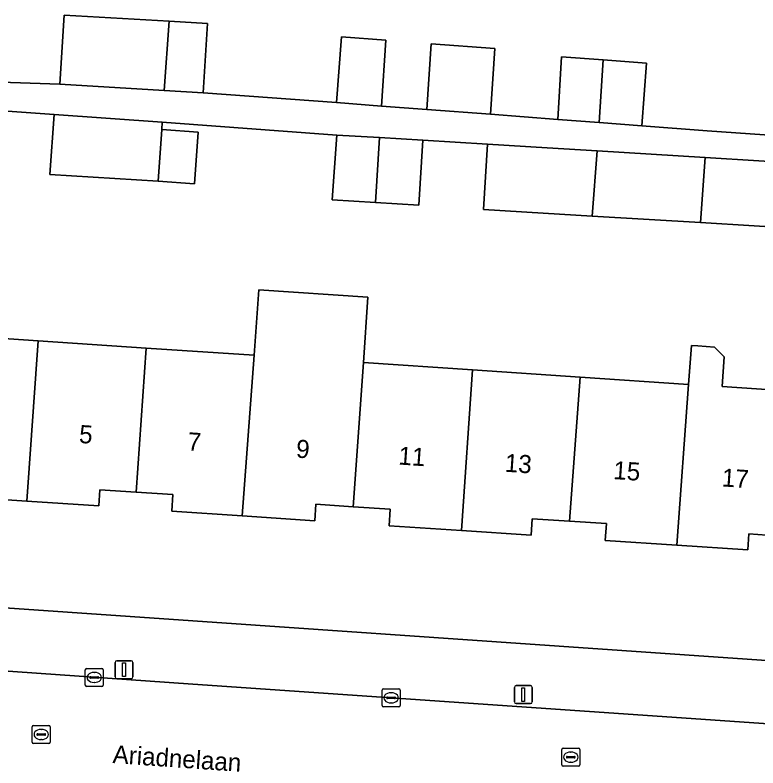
# Model space of a CAD drawing. Extents: x 161848 to 162726, y 385382 to 386521.
# Drawn here: x 162033.12 to 162074.32, y 385520.46 to 385562.19 of the extents above; entities that cross this region are included whole.
import ezdxf

# ---------------------------------------------------------------- set-up
doc = ezdxf.new("R2010")
doc.units = 0
for name, color, linetype in [('IMGEO_Erf', 7, 'Continuous'), ('IMGEO_Kolk', 7, 'Continuous'), ('IMGEO_Lichtmast', 7, 'Continuous'), ('IMGEO_Openbare_ruimte_label', 7, 'Continuous'), ('IMGEO_Pand', 7, 'Continuous'), ('IMGEO_Pand_nummerreeks', 7, 'Continuous'), ('IMGEO_Rijbaan_lokaal_open', 7, 'Continuous'), ('IMGEO_Rioolput', 7, 'Continuous'), ('IMGEO_Voetpad_open', 7, 'Continuous')]:
    doc.layers.add(name, color=color, linetype=linetype)

msp = doc.modelspace()

# ---------------------------------------------------------------- linework, layer by layer
at = {"layer": 'IMGEO_Erf'}
for points in [[(162031.758, 385558.476), (162035.606, 385558.348), (162035.835, 385562.186), (162041.661, 385561.839), (162043.785, 385561.712), (162043.556, 385557.874), (162050.942, 385557.333), (162051.218, 385560.974), (162053.681, 385560.788), (162053.437, 385557.144), (162055.957, 385556.953), (162056.201, 385560.597), (162059.728, 385560.33), (162059.48, 385556.687), (162063.214, 385556.405), (162063.426, 385559.879), (162065.736, 385559.703), (162068.137, 385559.521), (162067.889, 385556.051), (162071.496, 385555.778), (162083.419, 385554.931)], [(162059.32, 385555.025), (162055.736, 385555.244), (162055.516, 385551.647), (162053.109, 385551.794), (162050.703, 385551.941), (162050.958, 385555.536), (162041.286, 385556.253), (162041.258, 385555.842), (162043.269, 385555.704), (162043.072, 385552.833), (162041.061, 385552.971), (162035.054, 385553.353), (162035.289, 385556.672), (162031.648, 385556.926), (162031.387, 385553.375), (162031.148, 385550.134), (162028.864, 385550.302), (162026.141, 385550.502), (162026.329, 385553.046), (162022.838, 385553.268), (162014.712, 385553.868), (162013.874, 385541.566), (162013.328, 385533.953)], [(162091.723, 385527.993), (162092.1, 385533.688), (162092.534, 385540.24), (162093.077, 385548.435), (162093.358, 385552.663), (162090.214, 385552.863), (162089.88, 385548.648), (162089.229, 385548.691), (162082.901, 385549.112), (162082.968, 385549.956), (162077.085, 385550.316), (162071.126, 385550.681), (162065.134, 385551.048), (162062.406, 385551.215), (162059.099, 385551.418), (162059.32, 385555.025)], [(162028.431, 385544.533), (162034.4, 385544.133), (162040.398, 385543.731), (162046.373, 385543.331), (162046.638, 385546.964), (162052.692, 385546.546), (162052.437, 385542.925), (162058.492, 385542.519), (162064.463, 385542.12), (162070.474, 385541.717), (162070.631, 385543.878), (162070.981, 385543.852), (162071.911, 385543.785), (162072.453, 385543.249), (162072.333, 385541.592), (162076.413, 385541.319)], [(162075.813, 385533.294), (162073.82, 385533.427), (162073.761, 385532.541), (162069.827, 385532.804), (162065.854, 385533.07), (162065.916, 385533.998), (162063.864, 385534.135), (162061.803, 385534.273), (162061.741, 385533.353), (162057.871, 385533.612), (162053.861, 385533.881), (162053.922, 385534.795), (162051.875, 385534.932), (162049.799, 385535.071), (162049.738, 385534.162), (162045.724, 385534.431), (162041.813, 385534.693), (162041.874, 385535.609), (162039.839, 385535.745), (162037.823, 385535.88), (162037.763, 385534.98), (162033.771, 385535.247), (162029.858, 385535.509)], [(162016.402, 385530.453), (162018.636, 385530.301), (162087.624, 385525.529), (162089.014, 385525.433)]]:
    msp.add_lwpolyline(points, dxfattribs=at)
at = {"layer": 'IMGEO_Kolk'}
for p, q in [((162037.014, 385525.047), (162037.014, 385525.899)), ((162037.089, 385525.973), (162037.941, 385525.973)), ((162038.015, 385525.899), (162038.015, 385525.047)), ((162037.273, 385525.467), (162037.273, 385525.479)), ((162037.316, 385525.516), (162037.714, 385525.516)), ((162037.502, 385525.753), (162037.527, 385525.753)), ((162037.757, 385525.479), (162037.757, 385525.467)), ((162037.711, 385525.43), (162037.313, 385525.43)), ((162037.525, 385525.193), (162037.5, 385525.193)), ((162037.941, 385524.973), (162037.089, 385524.973)), ((162053.474, 385523.918), (162053.474, 385524.77)), ((162053.549, 385524.844), (162054.401, 385524.844)), ((162054.475, 385524.77), (162054.475, 385523.918)), ((162053.733, 385524.338), (162053.733, 385524.35)), ((162054.171, 385524.301), (162053.773, 385524.301)), ((162053.776, 385524.387), (162054.174, 385524.387)), ((162053.962, 385524.624), (162053.987, 385524.624)), ((162054.217, 385524.35), (162054.217, 385524.338)), ((162054.401, 385523.844), (162053.549, 385523.844)), ((162053.985, 385524.064), (162053.96, 385524.064))]:
    msp.add_line(p, q, dxfattribs=at)
for points in [[(162037.014, 385525.047), (162037.014, 385525.899)], [(162037.089, 385525.973), (162037.941, 385525.973)], [(162038.015, 385525.899), (162038.015, 385525.047)], [(162037.941, 385524.973), (162037.089, 385524.973)], [(162053.474, 385523.918), (162053.474, 385524.77)], [(162053.549, 385524.844), (162054.401, 385524.844)], [(162054.475, 385524.77), (162054.475, 385523.918)], [(162054.401, 385523.844), (162053.549, 385523.844)]]:
    msp.add_lwpolyline(points, dxfattribs=at)
for centre, radius, start, end in [((162037.091, 385525.897), 0.0765, 91.552, 178.448), ((162037.091, 385525.897), 0.0765, 91.552, 178.448), ((162037.939, 385525.897), 0.0765, 1.552, 88.448), ((162037.939, 385525.897), 0.0765, 1.552, 88.448), ((162037.313, 385525.476), 0.0403, 85.8775, 175.7526), ((162037.31, 385525.466), 0.0366, 178.938, 274.7102), ((162037.714, 385525.473), 0.043, 264.8664, 352.4533), ((162037.718, 385525.478), 0.0386, 1.7309, 96.639), ((162037.091, 385525.049), 0.0765, 181.552, 268.448), ((162037.091, 385525.049), 0.0765, 181.552, 268.448), ((162037.939, 385525.049), 0.0765, 271.552, 358.448), ((162037.939, 385525.049), 0.0765, 271.552, 358.448), ((162053.551, 385524.768), 0.0765, 91.552, 178.448), ((162053.551, 385524.768), 0.0765, 91.552, 178.448), ((162054.399, 385524.768), 0.0765, 1.552, 88.448), ((162054.399, 385524.768), 0.0765, 1.552, 88.448), ((162053.773, 385524.347), 0.0403, 85.8775, 175.7526), ((162053.77, 385524.337), 0.0366, 178.938, 274.7102), ((162054.174, 385524.344), 0.043, 264.8664, 352.4533), ((162054.178, 385524.349), 0.0386, 1.7309, 96.639), ((162053.551, 385523.92), 0.0765, 181.552, 268.448), ((162053.551, 385523.92), 0.0765, 181.552, 268.448), ((162054.399, 385523.92), 0.0765, 271.552, 358.448), ((162054.399, 385523.92), 0.0765, 271.552, 358.448)]:
    msp.add_arc(centre, radius, start, end, dxfattribs=at)
for centre, major_axis, ratio, start_param, end_param in [((162037.501, 385525.473), (-0.387, 0.002), 0.722429, 4.712389, 7.853982), ((162037.526, 385525.473), (-0.39, 0.002), 0.717154, 1.570796, 4.712389), ((162053.961, 385524.344), (-0.387, 0.002), 0.722429, 4.712389, 7.853982), ((162053.986, 385524.344), (-0.39, 0.002), 0.717154, 1.570796, 4.712389)]:
    msp.add_ellipse(centre, major_axis=major_axis, ratio=ratio, start_param=start_param, end_param=end_param, dxfattribs=at)
at = {"layer": 'IMGEO_Lichtmast'}
for p, q in [((162038.668, 385525.501), (162038.668, 385526.301)), ((162038.668, 385526.301), (162038.668, 385525.501)), ((162038.768, 385526.401), (162039.558, 385526.401)), ((162039.558, 385526.401), (162038.768, 385526.401)), ((162039.658, 385526.301), (162039.658, 385525.501)), ((162039.658, 385525.501), (162039.658, 385526.301)), ((162039.558, 385525.401), (162038.768, 385525.401)), ((162038.768, 385525.401), (162039.558, 385525.401)), ((162060.81, 385524.124), (162060.81, 385524.924)), ((162060.81, 385524.924), (162060.81, 385524.124)), ((162060.91, 385525.024), (162061.7, 385525.024)), ((162061.7, 385525.024), (162060.91, 385525.024)), ((162061.8, 385524.924), (162061.8, 385524.124)), ((162061.8, 385524.124), (162061.8, 385524.924)), ((162061.7, 385524.024), (162060.91, 385524.024)), ((162060.91, 385524.024), (162061.7, 385524.024))]:
    msp.add_line(p, q, dxfattribs=at)
for points in [[(162039.088, 385526.276), (162039.238, 385526.276), (162039.238, 385525.526), (162039.088, 385525.526), (162039.088, 385526.276)], [(162061.23, 385524.899), (162061.38, 385524.899), (162061.38, 385524.149), (162061.23, 385524.149), (162061.23, 385524.899)]]:
    msp.add_lwpolyline(points, dxfattribs=at)
for centre, start, end in [((162038.768, 385526.301), 90, 180), ((162038.768, 385526.301), 90, 180), ((162039.558, 385526.301), 0, 90), ((162039.558, 385526.301), 360, 90), ((162038.768, 385525.501), 180, 270), ((162038.768, 385525.501), 180, 270), ((162039.558, 385525.501), 270, 0), ((162039.558, 385525.501), 270, 0), ((162060.91, 385524.924), 90, 180), ((162060.91, 385524.924), 90, 180), ((162061.7, 385524.924), 0, 90), ((162061.7, 385524.924), 360, 90), ((162060.91, 385524.124), 180, 270), ((162060.91, 385524.124), 180, 270), ((162061.7, 385524.124), 270, 0), ((162061.7, 385524.124), 270, 0)]:
    msp.add_arc(centre, 0.1, start, end, dxfattribs=at)
at = {"layer": 'IMGEO_Pand'}
for points in [[(162035.835, 385562.186), (162035.606, 385558.348), (162041.398, 385558.003), (162041.661, 385561.839)], [(162043.556, 385557.874), (162043.785, 385561.712), (162041.661, 385561.839), (162041.398, 385558.003)], [(162053.681, 385560.788), (162051.218, 385560.974), (162050.942, 385557.333), (162053.437, 385557.144)], [(162055.957, 385556.953), (162059.48, 385556.687), (162059.728, 385560.33), (162056.201, 385560.597)], [(162065.736, 385559.703), (162063.426, 385559.879), (162063.214, 385556.405), (162065.523, 385556.23)], [(162065.736, 385559.703), (162065.523, 385556.23), (162067.889, 385556.051), (162068.137, 385559.521)], [(162041.258, 385555.842), (162041.286, 385556.253), (162035.289, 385556.672), (162035.054, 385553.353), (162041.061, 385552.971)], [(162041.061, 385552.971), (162043.072, 385552.833), (162043.269, 385555.704), (162041.258, 385555.842)], [(162053.109, 385551.794), (162053.329, 385555.391), (162050.958, 385555.536), (162050.703, 385551.941)], [(162053.329, 385555.391), (162053.109, 385551.794), (162055.516, 385551.647), (162055.736, 385555.244)], [(162065.405, 385554.653), (162062.627, 385554.823), (162059.32, 385555.025), (162059.099, 385551.418), (162062.406, 385551.215), (162065.134, 385551.048)], [(162065.134, 385551.048), (162071.126, 385550.681), (162071.388, 385554.286), (162065.405, 385554.653)], [(162071.126, 385550.681), (162077.085, 385550.316), (162077.354, 385553.921), (162071.388, 385554.286)], [(162052.437, 385542.925), (162052.692, 385546.546), (162046.638, 385546.964), (162046.373, 385543.331), (162045.724, 385534.431), (162049.738, 385534.162), (162049.799, 385535.071), (162051.875, 385534.932)], [(162034.4, 385544.133), (162028.431, 385544.533), (162027.865, 385536.544), (162029.919, 385536.407), (162029.858, 385535.509), (162033.771, 385535.247)], [(162040.398, 385543.731), (162034.4, 385544.133), (162033.771, 385535.247), (162037.763, 385534.98), (162037.823, 385535.88), (162039.839, 385535.745)], [(162076.413, 385541.319), (162072.333, 385541.592), (162072.453, 385543.249), (162071.911, 385543.785), (162070.981, 385543.852), (162070.631, 385543.878), (162070.474, 385541.717), (162069.827, 385532.804), (162073.761, 385532.541), (162073.82, 385533.427), (162075.813, 385533.294)], [(162039.839, 385535.745), (162041.874, 385535.609), (162041.813, 385534.693), (162045.724, 385534.431), (162046.373, 385543.331), (162040.398, 385543.731)], [(162058.492, 385542.519), (162052.437, 385542.925), (162051.875, 385534.932), (162053.922, 385534.795), (162053.861, 385533.881), (162057.871, 385533.612)], [(162064.463, 385542.12), (162058.492, 385542.519), (162057.871, 385533.612), (162061.741, 385533.353), (162061.803, 385534.273), (162063.864, 385534.135)], [(162063.864, 385534.135), (162065.916, 385533.998), (162065.854, 385533.07), (162069.827, 385532.804), (162070.474, 385541.717), (162064.463, 385542.12)]]:
    msp.add_lwpolyline(points, close=True, dxfattribs=at)
at = {"layer": 'IMGEO_Rijbaan_lokaal_open'}
for points in [[(162042.972, 385525.1), (162018.004, 385526.862), (162015.014, 385527.081), (162014.628, 385519.918), (162018.299, 385519.675), (162054.531, 385517.227), (162072.879, 385515.977)], [(162086.98, 385522.071), (162042.972, 385525.1)]]:
    msp.add_lwpolyline(points, dxfattribs=at)
at = {"layer": 'IMGEO_Rioolput'}
for p, q in [((162034.073, 385521.886), (162034.073, 385522.738)), ((162034.148, 385522.812), (162035, 385522.812)), ((162034.561, 385522.592), (162034.586, 385522.592)), ((162035.074, 385522.738), (162035.074, 385521.886)), ((162034.332, 385522.306), (162034.332, 385522.318)), ((162034.77, 385522.269), (162034.372, 385522.269)), ((162034.375, 385522.355), (162034.773, 385522.355)), ((162034.816, 385522.318), (162034.816, 385522.306)), ((162035, 385521.812), (162034.148, 385521.812)), ((162034.584, 385522.032), (162034.559, 385522.032)), ((162063.438, 385520.63), (162063.438, 385521.482)), ((162063.513, 385521.556), (162064.365, 385521.556)), ((162063.926, 385521.336), (162063.951, 385521.336)), ((162064.439, 385521.482), (162064.439, 385520.63)), ((162063.697, 385521.05), (162063.697, 385521.062)), ((162064.135, 385521.013), (162063.737, 385521.013)), ((162063.74, 385521.099), (162064.138, 385521.099)), ((162064.181, 385521.062), (162064.181, 385521.05)), ((162064.365, 385520.556), (162063.513, 385520.556)), ((162063.949, 385520.776), (162063.924, 385520.776))]:
    msp.add_line(p, q, dxfattribs=at)
for points in [[(162034.073, 385521.886), (162034.073, 385522.738)], [(162034.148, 385522.812), (162035, 385522.812)], [(162035.074, 385522.738), (162035.074, 385521.886)], [(162035, 385521.812), (162034.148, 385521.812)], [(162063.438, 385520.63), (162063.438, 385521.482)], [(162063.513, 385521.556), (162064.365, 385521.556)], [(162064.439, 385521.482), (162064.439, 385520.63)], [(162064.365, 385520.556), (162063.513, 385520.556)]]:
    msp.add_lwpolyline(points, dxfattribs=at)
for centre, radius, start, end in [((162034.15, 385522.736), 0.0765, 91.552, 178.448), ((162034.15, 385522.736), 0.0765, 91.552, 178.448), ((162034.998, 385522.736), 0.0765, 1.552, 88.448), ((162034.998, 385522.736), 0.0765, 1.552, 88.448), ((162034.372, 385522.315), 0.0403, 85.8775, 175.7526), ((162034.369, 385522.305), 0.0366, 178.938, 274.7102), ((162034.773, 385522.312), 0.043, 264.8664, 352.4533), ((162034.777, 385522.317), 0.0386, 1.7309, 96.639), ((162034.15, 385521.888), 0.0765, 181.552, 268.448), ((162034.15, 385521.888), 0.0765, 181.552, 268.448), ((162034.998, 385521.888), 0.0765, 271.552, 358.448), ((162034.998, 385521.888), 0.0765, 271.552, 358.448), ((162063.515, 385521.48), 0.0765, 91.552, 178.448), ((162063.515, 385521.48), 0.0765, 91.552, 178.448), ((162064.363, 385521.48), 0.0765, 1.552, 88.448), ((162064.363, 385521.48), 0.0765, 1.552, 88.448), ((162063.737, 385521.059), 0.0403, 85.8775, 175.7526), ((162063.734, 385521.049), 0.0366, 178.938, 274.7102), ((162064.138, 385521.056), 0.043, 264.8664, 352.4533), ((162064.142, 385521.061), 0.0386, 1.7309, 96.639), ((162063.515, 385520.632), 0.0765, 181.552, 268.448), ((162063.515, 385520.632), 0.0765, 181.552, 268.448), ((162064.363, 385520.632), 0.0765, 271.552, 358.448), ((162064.363, 385520.632), 0.0765, 271.552, 358.448)]:
    msp.add_arc(centre, radius, start, end, dxfattribs=at)
for centre, major_axis, ratio, start_param, end_param in [((162034.56, 385522.312), (-0.387, 0.002), 0.722429, 4.712389, 7.853982), ((162034.585, 385522.312), (-0.39, 0.002), 0.717154, 1.570796, 4.712389), ((162063.925, 385521.056), (-0.387, 0.002), 0.722429, 4.712389, 7.853982), ((162063.95, 385521.056), (-0.39, 0.002), 0.717154, 1.570796, 4.712389)]:
    msp.add_ellipse(centre, major_axis=major_axis, ratio=ratio, start_param=start_param, end_param=end_param, dxfattribs=at)
at = {"layer": 'IMGEO_Voetpad_open'}
for points in [[(162083.419, 385554.931), (162071.496, 385555.778), (162067.889, 385556.051), (162065.523, 385556.23), (162063.214, 385556.405), (162059.48, 385556.687), (162055.957, 385556.953), (162053.437, 385557.144), (162050.942, 385557.333), (162043.556, 385557.874), (162041.398, 385558.003), (162035.606, 385558.348), (162031.758, 385558.476)], [(162031.648, 385556.926), (162035.289, 385556.672), (162041.286, 385556.253), (162050.958, 385555.536), (162053.329, 385555.391), (162055.736, 385555.244), (162059.32, 385555.025), (162062.627, 385554.823), (162065.405, 385554.653), (162071.388, 385554.286), (162077.354, 385553.921)], [(162089.014, 385525.433), (162087.624, 385525.529), (162018.636, 385530.301)], [(162015.014, 385527.081), (162018.004, 385526.862), (162042.972, 385525.1), (162086.98, 385522.071)]]:
    msp.add_lwpolyline(points, dxfattribs=at)

# ---------------------------------------------------------------- texts
at = {"layer": 'IMGEO_Openbare_ruimte_label'}
msp.add_text('Ariadnelaan', height=1, rotation=356.1021, dxfattribs=at).set_placement((162038.511, 385520.729))
at = {"layer": 'IMGEO_Pand_nummerreeks'}
for s, rotation, p in [('5', 356.1313, (162036.647, 385538.475)), ('7', 356.1313, (162042.664, 385538.068)), ('9', 356.1325, (162048.682, 385537.662)), ('11', 356.1313, (162054.355, 385537.278)), ('13', 356.1313, (162060.258, 385536.878)), ('15', 356.1313, (162066.275, 385536.471)), ('17', 356.1325, (162072.292, 385536.064))]:
    msp.add_text(s, height=1, rotation=rotation, dxfattribs=at).set_placement(p)

doc.saveas('drawing.dxf')
